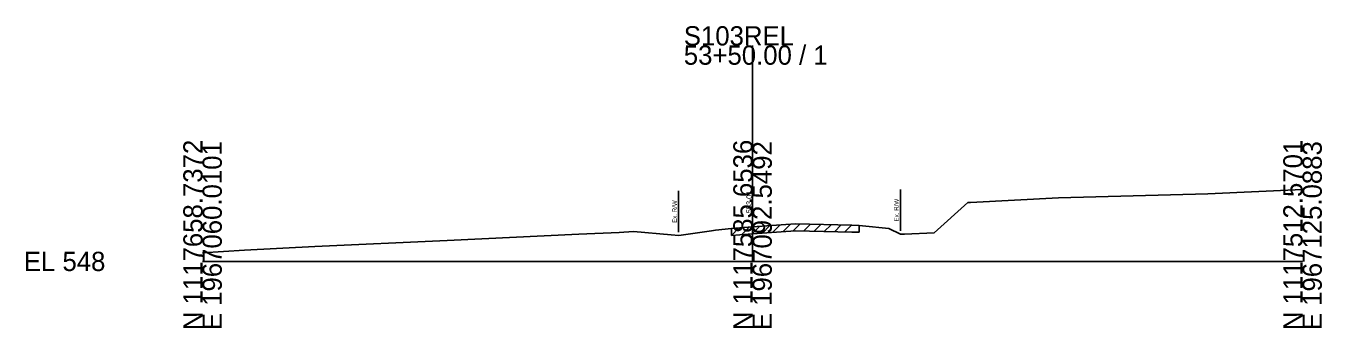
# Model space of a CAD drawing. Extents: x -26 to 163, y -10 to 24518.
# Drawn here: x -25.7 to 162.8, y 3990.3 to 4034.2 of the extents above; entities that cross this region are included whole.
import ezdxf

# ---------------------------------------------------------------- set-up
doc = ezdxf.new("R2010")
doc.units = 0
for name, color, linetype in [('RD_GPK_XS_Cell', 7, 'Continuous'), ('RD_XS_ExGround', 7, 'Continuous'), ('RD_XS_ExPaveRet', 7, 'Continuous'), ('RD_XS_ExRW', 7, 'Continuous'), ('RD_XS_TX_Elev_EX', 7, 'Continuous')]:
    doc.layers.add(name, color=color, linetype=linetype)

msp = doc.modelspace()

# ---------------------------------------------------------------- linework, layer by layer
at = {"layer": 'RD_GPK_XS_Cell'}
for p, q in [((80, 4000), (80, 4031.4)), ((0, 4000), (80, 4000)), ((80, 4000), (160, 4000))]:
    msp.add_line(p, q, dxfattribs=at)
at = {"layer": 'RD_XS_ExGround'}
msp.add_lwpolyline([(0, 4001.26), (6.08, 4001.65), (16.34, 4002.16), (35.58, 4003.06), (54.74, 4003.97), (60.59, 4004.22), (62.66, 4004.34), (68.18, 4003.86), (69.26, 4003.76), (74.01, 4004.43), (74.63, 4004.54), (76.93, 4004.78), (78.13, 4004.88), (80, 4005.01), (86.24, 4005.47), (94.46, 4005.26), (95.49, 4005.23), (95.99, 4005.18), (99.81, 4004.79), (101.52, 4003.97), (102.12, 4003.98), (106.43, 4004.17), (111.32, 4008.56), (111.71, 4008.58), (124.52, 4009.26), (146.23, 4009.81), (160, 4010.47)], dxfattribs=at)
at = {"layer": 'RD_XS_ExPaveRet'}
for p, q in [((76.93, 4003.78), (78.02, 4004.87)), ((76.93, 4003.78), (76.93, 4004.78)), ((78.43, 4003.9), (79.51, 4004.98)), ((79.93, 4004.01), (81.01, 4005.09)), ((80, 4004.01), (86.24, 4004.47)), ((81.43, 4004.12), (82.51, 4005.2)), ((82.93, 4004.23), (84.01, 4005.31)), ((84.43, 4004.34), (85.51, 4005.42)), ((85.93, 4004.45), (86.94, 4005.45)), ((86.24, 4004.47), (94.46, 4004.26)), ((87.44, 4004.44), (88.41, 4005.41)), ((88.94, 4004.4), (89.91, 4005.38)), ((90.44, 4004.36), (91.41, 4005.34)), ((91.94, 4004.32), (92.91, 4005.3)), ((93.44, 4004.28), (94.41, 4005.26)), ((95.49, 4005.23), (95.49, 4004.23)), ((76.93, 4003.78), (78.13, 4003.88)), ((78.13, 4003.88), (80, 4004.01)), ((94.46, 4004.26), (95.49, 4004.23))]:
    msp.add_line(p, q, dxfattribs=at)
at = {"layer": 'RD_XS_ExRW'}
for p, q in [((69.24, 4010.26), (69.24, 4004.26)), ((101.52, 4010.47), (101.52, 4004.47))]:
    msp.add_line(p, q, dxfattribs=at)

# ---------------------------------------------------------------- texts
at = {"layer": 'RD_GPK_XS_Cell'}
for s, p in [('S103REL', (70, 4031.4)), ('53+50.00 / 1', (70, 4028.6)), ('EL 548', (-26, 3998.6))]:
    msp.add_text(s, height=2.8, dxfattribs=at).set_placement(p)
for s, p in [('N 1117658.7372', (0, 3990)), ('E 1967060.0101', (2.8, 3990)), ('N 1117585.6536', (80, 3990)), ('E 1967092.5492', (82.8, 3990)), ('N 1117512.5701', (160, 3990)), ('E 1967125.0883', (162.8, 3990))]:
    msp.add_text(s, height=2.8, rotation=90, dxfattribs=at).set_placement(p)
at = {"layer": 'RD_XS_ExRW'}
for p in [(68.99, 4005.6), (101.27, 4005.81)]:
    msp.add_text('Ex. R/W ', height=0.65, rotation=90, dxfattribs=at).set_placement(p)
at = {"layer": 'RD_XS_TX_Elev_EX'}
msp.add_text('553.01', height=0.8, rotation=90, dxfattribs=at).set_placement((79.9, 4007.01))

doc.saveas('drawing.dxf')
